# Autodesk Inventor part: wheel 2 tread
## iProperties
Created: 2010-10
Part Number: wheel 2 tread
Document SubType Name: Modeling
Designer: Administrator
Density: 0.93 g/cm^3
Material: Rubber
Mass: 85.9208 g
Surface Area: 201.061 cm^2
Volume: 92.3879 cm^3
Author: Administrator
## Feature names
1. Base1
